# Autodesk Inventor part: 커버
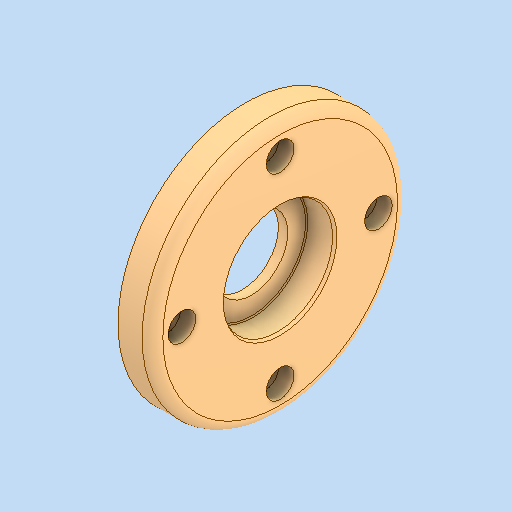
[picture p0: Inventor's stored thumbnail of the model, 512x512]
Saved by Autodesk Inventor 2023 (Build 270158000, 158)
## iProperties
Created: 2024-11
Part Number: 커버
Material: 알루미늄 6061
Document SubType Name: Modeling
Designer: asung
Density: 2.7 g/cm^3
Appearance: 기본값
Author: jhkim
Sending System: Autodesk Inventor 2025
Preprocessor: ST-DEVELOPER v20
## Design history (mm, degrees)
feature "솔리드1"
node "솔리드2"
